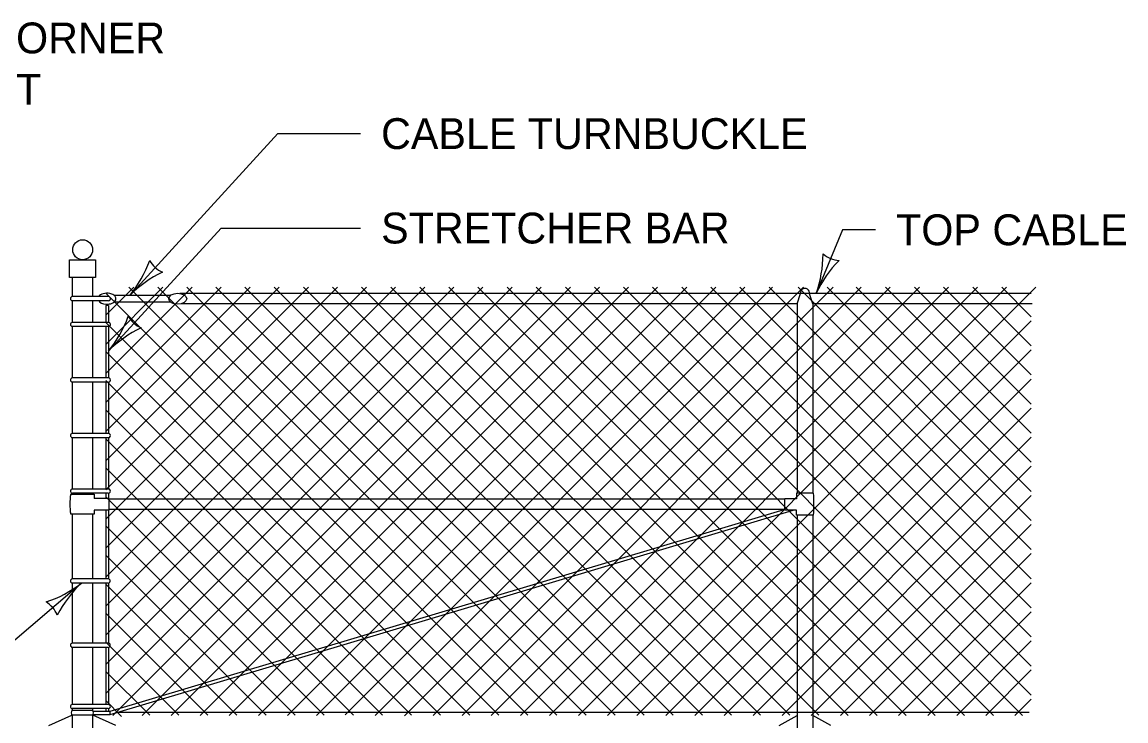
# Model space of a CAD drawing. Extents: x 49973.1 to 50021, y 49987.6 to 50015.4.
# Drawn here: x 49978.181 to 49980.327, y 50013.962 to 50015.321 of the extents above; entities that cross this region are included whole.
import ezdxf

# ---------------------------------------------------------------- set-up
doc = ezdxf.new("R2010")
doc.units = 0
for name, color, linetype in [('Level 1', 7, 'Continuous'), ('Level 2', 7, 'Continuous'), ('Level 3', 7, 'Continuous')]:
    doc.layers.add(name, color=color, linetype=linetype)

msp = doc.modelspace()

# ---------------------------------------------------------------- linework, layer by layer
at = {"layer": 'Level 1'}
for p, q in [((49978.2782, 50014.8243), (49978.2782, 50014.7871)), ((49978.3182, 50014.8243), (49978.3182, 50014.7871)), ((49978.7942, 50014.8053), (49978.3436, 50014.3547)), ((49978.3983, 50014.8053), (49978.3438, 50014.7509)), ((49978.4549, 50014.8053), (49978.3438, 50014.6943)), ((49978.5115, 50014.8053), (49978.3438, 50014.6377)), ((49978.5681, 50014.8053), (49978.3438, 50014.581)), ((49978.6811, 50014.8053), (49978.3438, 50014.468)), ((49978.6245, 50014.8053), (49978.3438, 50014.5246)), ((49978.7379, 50014.8053), (49978.3438, 50014.4115)), ((49979.1336, 50014.8053), (49978.3438, 50014.0155)), ((49979.0205, 50014.8053), (49978.3438, 50014.1286)), ((49978.9641, 50014.8053), (49978.3438, 50014.185)), ((49978.9074, 50014.8053), (49978.3438, 50014.2417)), ((49978.8509, 50014.8053), (49978.3438, 50014.2982)), ((49979.077, 50014.8053), (49978.3438, 50014.0721)), ((49979.1646, 50013.973), (49978.3438, 50014.7938)), ((49979.1902, 50014.8053), (49978.3578, 50013.9729)), ((49979.221, 50013.973), (49978.3883, 50014.8053)), ((49979.2472, 50014.8053), (49978.4144, 50013.9729)), ((49979.2776, 50013.973), (49978.4447, 50014.8053)), ((49979.3034, 50014.8053), (49978.471, 50013.9729)), ((49979.3342, 50013.973), (49978.5015, 50014.8053)), ((49979.3598, 50014.8053), (49978.5274, 50013.9729)), ((49979.3908, 50013.973), (49978.5577, 50014.8053)), ((49979.4164, 50014.8053), (49978.584, 50013.9729)), ((49979.4472, 50013.973), (49978.6144, 50014.8053)), ((49979.4734, 50014.8053), (49978.6406, 50013.9729)), ((49979.5038, 50013.973), (49978.6711, 50014.8053)), ((49979.53, 50014.8053), (49978.6972, 50013.9729)), ((49979.5604, 50013.973), (49978.728, 50014.8053)), ((49979.5862, 50014.8053), (49978.7538, 50013.9729)), ((49979.617, 50013.973), (49978.7844, 50014.8053)), ((49979.6404, 50014.8053), (49978.8092, 50013.9741)), ((49979.6736, 50013.973), (49978.8411, 50014.8053)), ((49979.7005, 50014.8053), (49978.8675, 50013.9724)), ((49979.7302, 50013.973), (49978.8978, 50014.8053)), ((49979.7579, 50014.8053), (49978.9244, 50013.9719)), ((49979.7869, 50013.9729), (49978.9541, 50014.8053)), ((49979.8125, 50014.8053), (49978.98, 50013.9729)), ((49979.8433, 50013.9729), (49979.0108, 50014.8053)), ((49979.8691, 50014.8053), (49979.0366, 50013.9729)), ((49979.8999, 50013.9729), (49979.0674, 50014.8053)), ((49979.9257, 50014.8053), (49979.0932, 50013.9729)), ((49979.9565, 50013.9729), (49979.1241, 50014.8053)), ((49979.9823, 50014.8053), (49979.1498, 50013.9729)), ((49980.0131, 50013.9729), (49979.1807, 50014.8053)), ((49980.0389, 50014.8053), (49979.2064, 50013.9729)), ((49980.0697, 50013.9729), (49979.2373, 50014.8053)), ((49980.0953, 50014.8053), (49979.2628, 50013.9729)), ((49980.1263, 50013.9729), (49979.2939, 50014.8053)), ((49980.1519, 50014.8053), (49979.3194, 50013.9729)), ((49980.1432, 50014.0123), (49979.3503, 50014.8053)), ((49980.1432, 50014.0689), (49979.4069, 50014.8053)), ((49980.1432, 50014.1255), (49979.4635, 50014.8053)), ((49980.1432, 50014.1821), (49979.5201, 50014.8053)), ((49980.1432, 50014.2387), (49979.5767, 50014.8053)), ((49980.1432, 50014.2953), (49979.6333, 50014.8053)), ((49980.1432, 50014.3519), (49979.6899, 50014.8053)), ((49980.1432, 50014.4083), (49979.7463, 50014.8053)), ((49980.1432, 50014.4649), (49979.8029, 50014.8053)), ((49980.1432, 50014.5215), (49979.8595, 50014.8053)), ((49980.1432, 50014.5781), (49979.9161, 50014.8053)), ((49980.1432, 50014.6347), (49979.9727, 50014.8053)), ((49980.1432, 50014.6913), (49980.0293, 50014.8053)), ((49980.1432, 50014.7478), (49980.0857, 50014.8053)), ((49978.2782, 50014.7791), (49978.2782, 50014.7369)), ((49978.3489, 50014.7871), (49978.2783, 50014.7871)), ((49978.3488, 50014.779), (49978.2784, 50014.779)), ((49978.3182, 50014.779), (49978.3182, 50014.7369)), ((49978.4696, 50014.7762), (49978.3594, 50014.7762)), ((49978.4698, 50014.7895), (49978.3604, 50014.7894)), ((49980.1432, 50014.7932), (49978.4879, 50014.7932)), ((49979.6882, 50014.7732), (49978.4911, 50014.7732)), ((49979.6882, 50014.7732), (49979.6942, 50014.793)), ((49979.6882, 50014.7732), (49979.6882, 50014.405)), ((49979.7182, 50014.7732), (49979.7119, 50014.7927)), ((49980.1448, 50014.7732), (49979.7182, 50014.7732)), ((49979.7182, 50014.7732), (49979.7182, 50014.405)), ((49978.3488, 50014.7695), (49978.3438, 50014.7695)), ((49978.3438, 50014.7695), (49978.3438, 50014.75)), ((49978.3488, 50014.7695), (49978.3488, 50014.7369)), ((49978.3487, 50014.7369), (49978.2783, 50014.7369)), ((49978.3438, 50014.75), (49978.3438, 50014.7369)), ((49979.108, 50013.973), (49978.3438, 50014.7369)), ((49980.1432, 50014.7401), (49979.376, 50013.9729)), ((49978.2782, 50014.7289), (49978.2782, 50014.6289)), ((49978.3491, 50014.7288), (49978.2784, 50014.7288)), ((49978.3182, 50014.7288), (49978.3182, 50014.6289)), ((49978.3438, 50014.7288), (49978.3438, 50014.6289)), ((49978.3488, 50014.7288), (49978.3488, 50014.6289)), ((49979.0514, 50013.973), (49978.3438, 50014.6803)), ((49980.1432, 50014.6834), (49979.4326, 50013.9729)), ((49978.3487, 50014.6289), (49978.2783, 50014.6289)), ((49978.9948, 50013.973), (49978.3438, 50014.6238)), ((49980.1432, 50014.6268), (49979.4892, 50013.9729)), ((49978.2782, 50014.6209), (49978.2782, 50014.5209)), ((49978.3487, 50014.6208), (49978.2784, 50014.6208)), ((49978.3182, 50014.6208), (49978.3182, 50014.5209)), ((49978.3438, 50014.6208), (49978.3438, 50014.5209)), ((49978.3488, 50014.6208), (49978.3488, 50014.5209)), ((49978.9382, 50013.973), (49978.3438, 50014.5671)), ((49980.1432, 50014.5702), (49979.5458, 50013.9729)), ((49978.3487, 50014.5209), (49978.2783, 50014.5209)), ((49978.2782, 50014.5129), (49978.2782, 50014.4129)), ((49978.3487, 50014.5128), (49978.2784, 50014.5128)), ((49978.3182, 50014.5128), (49978.3182, 50014.4129)), ((49978.3438, 50014.5128), (49978.3438, 50014.4129)), ((49978.8816, 50013.973), (49978.3438, 50014.5108)), ((49978.3488, 50014.5128), (49978.3488, 50014.4129)), ((49980.1432, 50014.5138), (49979.6022, 50013.9729)), ((49978.8252, 50013.973), (49978.3438, 50014.4542)), ((49980.1432, 50014.4572), (49979.6588, 50013.9729)), ((49978.3487, 50014.4129), (49978.278, 50014.4129)), ((49978.2782, 50014.405), (49978.2782, 50014.4031)), ((49978.3487, 50014.4048), (49978.2793, 50014.4048)), ((49978.3182, 50014.4048), (49978.3182, 50014.4031)), ((49978.3503, 50014.3947), (49978.3214, 50014.3947)), ((49978.3438, 50014.4048), (49978.3438, 50014.3947)), ((49978.7686, 50013.973), (49978.3438, 50014.3978)), ((49978.3488, 50014.4048), (49978.3488, 50014.3947)), ((49978.3503, 50014.3718), (49978.3503, 50014.3947)), ((49979.6638, 50014.3932), (49978.3503, 50014.3932)), ((49979.687, 50014.3942), (49979.6638, 50014.3942)), ((49979.6638, 50014.3721), (49979.6638, 50014.3942)), ((49979.7198, 50014.405), (49979.687, 50014.405)), ((49979.687, 50014.405), (49979.687, 50014.3942)), ((49980.1432, 50014.4006), (49979.7154, 50013.9729)), ((49978.3503, 50014.3718), (49978.3214, 50014.3718)), ((49978.3438, 50014.3718), (49978.3438, 50014.2382)), ((49978.3488, 50014.3718), (49978.3488, 50014.2382)), ((49979.6638, 50014.3732), (49978.3503, 50014.3732)), ((49978.3523, 50013.9811), (49979.6626, 50014.3732)), ((49978.3523, 50013.9747), (49979.6803, 50014.3721)), ((49979.6868, 50014.3721), (49979.6638, 50014.3721)), ((49979.6868, 50014.3624), (49979.6868, 50014.3721)), ((49978.2782, 50014.3641), (49978.2782, 50014.2382)), ((49978.3182, 50014.3641), (49978.3182, 50014.2382)), ((49979.7198, 50014.3624), (49979.6868, 50014.3624)), ((49979.6882, 50014.3624), (49979.6882, 50013.973)), ((49979.7182, 50014.3624), (49979.7182, 50013.973)), ((49980.1432, 50014.344), (49979.772, 50013.9729)), ((49978.712, 50013.973), (49978.3438, 50014.3412)), ((49978.6554, 50013.973), (49978.3438, 50014.2847)), ((49980.1432, 50014.2875), (49979.8286, 50013.9729)), ((49978.3485, 50014.2382), (49978.2783, 50014.2382)), ((49978.2782, 50014.2302), (49978.2782, 50014.1132)), ((49978.3482, 50014.2301), (49978.2784, 50014.2301)), ((49978.3182, 50014.2301), (49978.3182, 50014.1132)), ((49978.3438, 50014.2301), (49978.3438, 50014.1262)), ((49978.5988, 50013.973), (49978.3438, 50014.2281)), ((49978.3488, 50014.2302), (49978.3488, 50014.1132)), ((49980.1432, 50014.2308), (49979.8852, 50013.9729)), ((49978.5422, 50013.973), (49978.3438, 50014.1714)), ((49980.1432, 50014.1742), (49979.9418, 50013.9729)), ((49978.3485, 50014.1132), (49978.2783, 50014.1132)), ((49978.3438, 50014.1262), (49978.3438, 50014.1132)), ((49978.4858, 50013.973), (49978.3445, 50014.1143)), ((49980.1432, 50014.1178), (49979.9982, 50013.9729)), ((49978.2782, 50014.1052), (49978.2782, 50013.9941)), ((49978.3482, 50014.1051), (49978.2784, 50014.1051)), ((49978.3182, 50014.1051), (49978.3182, 50013.9941)), ((49978.3438, 50014.1051), (49978.3438, 50013.9941)), ((49978.3488, 50014.1052), (49978.3488, 50013.9941)), ((49978.4292, 50013.973), (49978.3442, 50014.058)), ((49980.1432, 50014.0613), (49980.0548, 50013.9729)), ((49978.3746, 50013.971), (49978.3438, 50014.0018)), ((49980.1432, 50014.0046), (49980.1114, 50013.9729)), ((49978.3184, 50013.9827), (49978.2779, 50013.9827)), ((49978.3484, 50013.9941), (49978.2782, 50013.9941)), ((49978.2782, 50013.9861), (49978.2782, 50013.9827)), ((49978.3484, 50013.986), (49978.2783, 50013.986)), ((49978.3182, 50013.986), (49978.3182, 50013.9827)), ((49978.3191, 50013.9811), (49978.3523, 50013.9811)), ((49978.3438, 50013.986), (49978.3438, 50013.9811)), ((49978.3488, 50013.986), (49978.3488, 50013.9811)), ((49978.3523, 50013.9747), (49978.3523, 50013.9811)), ((49980.1394, 50013.9785), (49978.365, 50013.9785)), ((49978.2332, 50013.9532), (49978.2779, 50013.9732)), ((49978.3183, 50013.9732), (49978.2779, 50013.9732)), ((49978.2782, 50013.9732), (49978.2782, 50013.5332)), ((49978.3182, 50013.9732), (49978.3182, 50013.5332)), ((49978.3632, 50013.9532), (49978.3183, 50013.9732)), ((49978.3191, 50013.9747), (49978.3523, 50013.9747)), ((49979.6532, 50013.9531), (49979.6882, 50013.9726)), ((49979.6882, 50013.973), (49979.6882, 50013.5332)), ((49979.7182, 50013.973), (49979.7182, 50013.5332)), ((49979.7532, 50013.9532), (49979.7182, 50013.9729))]:
    msp.add_line(p, q, dxfattribs=at)
msp.add_lwpolyline([(49978.3241, 50014.8586), (49978.3241, 50014.8243), (49978.2732, 50014.8243), (49978.2732, 50014.8586)], close=True, dxfattribs=at)
for points in [[(49978.2755, 50014.4031), (49978.3214, 50014.4031), (49978.3214, 50014.3947)], [(49978.3214, 50014.3718), (49978.3214, 50014.3641), (49978.2755, 50014.3641)]]:
    msp.add_lwpolyline(points, dxfattribs=at)
msp.add_circle((49978.2988, 50014.8782), 0.0194, dxfattribs=at)
for centre, radius, start, end in [((49979.7031, 50014.7942), 0.00895, 350.428, 187.6246), ((49978.2794, 50014.7831), 0.00417, 104.8473, 257.4184), ((49978.3489, 50014.7831), 0.00405, 269.3348, 90.4595), ((49978.2794, 50014.7329), 0.00417, 104.8473, 257.4184), ((49978.3489, 50014.7329), 0.00405, 273.176, 92.0788), ((49978.2794, 50014.6249), 0.00417, 104.8473, 257.4184), ((49978.3489, 50014.6249), 0.00405, 266.824, 92.0788), ((49978.2794, 50014.5169), 0.00417, 104.8473, 257.4184), ((49978.3489, 50014.5169), 0.00405, 270.7491, 92.0788), ((49978.3489, 50014.5169), 0.00405, 266.824, 270.7491), ((49978.2794, 50014.409), 0.00417, 109.5021, 270.4471), ((49978.3489, 50014.4089), 0.00405, 266.824, 92.0788), ((49978.3801, 50014.3836), 0.1063, 169.4297, 190.5658), ((49979.4686, 50014.3837), 0.2521, 355.155, 4.8478), ((49978.2794, 50014.2342), 0.00417, 104.8473, 257.4184), ((49978.3484, 50014.2342), 0.00405, 266.824, 87.9212), ((49978.2794, 50014.1092), 0.00417, 104.8473, 257.4184), ((49978.3484, 50014.1092), 0.00405, 266.824, 87.9212), ((49978.2793, 50013.9901), 0.00417, 104.8473, 257.4184), ((49978.2867, 50013.978), 0.00992, 151.3522, 208.5571), ((49978.3103, 50013.978), 0.00931, 329.2674, 30.6196), ((49978.3486, 50013.9901), 0.00405, 266.824, 92.0788)]:
    msp.add_arc(centre, radius, start, end, dxfattribs=at)
for start_param, end_param in [(4.569027, 9.026485), (3.521347, 4.569027), (4.855848, 4.855848)]:
    msp.add_ellipse((49978.3463, 50014.7831), major_axis=(0.0175, 0.0001), ratio=0.610393, start_param=start_param, end_param=end_param, dxfattribs=at)
msp.add_ellipse((49978.4836, 50014.7829), major_axis=(0.0175, 0.0001), ratio=0.610393, dxfattribs=at)
at = {"layer": 'Level 3'}
for p, q in [((49978.3904, 50014.7895), (49978.6785, 50015.104)), ((49978.6785, 50015.104), (49978.8391, 50015.104)), ((49978.3488, 50014.6812), (49978.568, 50014.9204)), ((49978.568, 50014.9204), (49978.8391, 50014.9204)), ((49979.7759, 50014.917), (49979.7251, 50014.7932)), ((49979.8404, 50014.917), (49979.7759, 50014.917)), ((49978.2964, 50014.2301), (49978.1485, 50014.1034))]:
    msp.add_line(p, q, dxfattribs=at)
for centre, radius, start, end in [((49979.5054, 50014.8709), 0.233, 340.529, 359.7789), ((49979.7737, 50014.9119), 0.0548, 229.8405, 265.5629), ((49978.2104, 50014.9374), 0.233, 320.5807, 339.8305), ((49978.4766, 50014.8844), 0.0548, 209.8922, 245.6145), ((49979.9271, 50014.7005), 0.2223, 135.1577, 155.3412), ((49978.5486, 50014.6333), 0.2223, 115.2094, 135.3929), ((49978.1689, 50014.8291), 0.233, 320.5807, 339.8305), ((49978.435, 50014.7761), 0.0548, 209.8922, 245.6145), ((49978.5071, 50014.525), 0.2223, 115.2094, 135.3929), ((49978.159, 50014.4048), 0.2223, 288.0156, 308.1991), ((49978.4565, 50014.0608), 0.233, 133.3869, 152.6368), ((49978.199, 50014.1468), 0.0548, 22.6984, 58.4208)]:
    msp.add_arc(centre, radius, start, end, dxfattribs=at)

# ---------------------------------------------------------------- texts
at = {"layer": 'Level 2'}
for s, p in [('GATE, END, CORNER', (49977.6344, 50015.26)), ('OR PULL POST', (49977.6344, 50015.16)), ('CABLE TURNBUCKLE', (49978.8791, 50015.074)), ('STRETCHER BAR', (49978.8791, 50014.8904)), ('TOP CABLE', (49979.8804, 50014.887))]:
    msp.add_text(s, height=0.06, dxfattribs=at).set_placement(p)

doc.saveas('drawing.dxf')
